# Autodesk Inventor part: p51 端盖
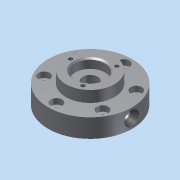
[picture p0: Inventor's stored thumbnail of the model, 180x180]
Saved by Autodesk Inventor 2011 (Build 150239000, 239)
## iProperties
Created: 2014-01
Part Number: p51 端盖
Document SubType Name: Modeling
Designer: Administrator
Density: 1 g/cm^3
Author: Administrator
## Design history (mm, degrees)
sketch "草图1"
  geometry: C1 r 45 at (0, 0); 1 further point
  constraints: 1 centre point, 1 coincident
  dimensions: "d0" = 90 diameter of C1
extrude "拉伸1" new body sketch "草图1" distance "d1" = 20; taper "d2" = 0 deg
sketch "草图2"
  geometry: C1 r 45 at (0, 0) reference; C2 r 26 at (0, 0)
  constraints: 1 centre point, 1 coincident
  dimensions: "d3" = 52 diameter of C2
extrude "拉伸2" join sketch "草图2" distance "d4" = 12; taper "d5" = 0 deg
sketch "草图3"
  geometry: C1 r 45 at (0, 0) reference; C2 r 27.5 at (0, 0)
  constraints: 1 centre point, 1 coincident
  dimensions: "d6" = 55 diameter of C2
extrude "拉伸3" join sketch "草图3" distance "d7" = 5; taper "d8" = 0 deg
hole "Hole1" diameter "d11" = 16; stored, may be unused: countersink angle "d15" = 90 deg, drill point angle "d17" = 0 deg; dims "d9" = 10, "d10" = 10, "d12" = 6, "d13" = 32, "d14" = 10, "d16" = 32
sketch "草图4" dims "d18" = 42
  geometry: C1 r 26 at (0, 0) reference; C2 r 3 at (-21, 0); 1 further point
  constraints: 1 centre point, 1 coincident, 1 horizontal alignment, 2 other
  dimensions: "d19" = 6 diameter of C2
hole "Hole2" sketch "草图4" at (-21, 0) diameter "d20" = 4.134; stored, may be unused: countersink angle "d24" = 90 deg, drill point angle "d26" = 118 deg; dims "d21" = 13, "d22" = 32, "d23" = 10, "d25" = 15
pattern_circular "环形阵列1" dims angle "d28" = 360 deg
sketch "草图5" dims "d30" = 72.5
  geometry: C1 r 45 at (0, 0) reference; C2 r 4.362 at (0, 36.25); 1 further point
  constraints: 1 centre point, 1 coincident, 1 vertical alignment, 2 other
hole "Hole3" sketch "草图5" at (0, 36.25) diameter "d31" = 6; stored, may be unused: countersink angle "d35" = 90 deg, drill point angle "d37" = 118 deg; dims "d32" = 13, "d33" = 12, "d34" = 6, "d36" = 15
pattern_circular "环形阵列2" dims angle "d39" = 360 deg
chamfer "倒角1" distance "d41" = 1.5; stored, may be unused: second distance "d42" = 2, angle "d43" = 45 deg
hole "Hole4" diameter "d46" = 35; stored, may be unused: countersink angle "d50" = 90 deg, drill point angle "d52" = 0 deg; dims "d44" = 10, "d45" = 10, "d47" = 13, "d48" = 12, "d49" = 6, "d51" = 5
fillet "圆角1" dims "d53" = 2
sketch "草图6"
  geometry: L1 (45, 0)-(45, 20) reference; L2 (-45, 20)-(45, 20) reference; L3 (-45, 0)-(45, 0) reference; L4 (-45, 0)-(-45, 20) reference; L5 (-45, 10)-(-45, 1.996); L6 (-45, 10)-(-37.745, 10); L7 (-37.745, 10)-(-37.745, 5); L8 (-37.745, 5)-(-45, 1.996); L9 (-37.745, 10)-(-16.745, 10); L10 (-16.745, 10)-(-16.745, 5); L11 (-16.745, 5)-(-37.745, 5); L12 (-16.745, 5)-(-12.099, 10); L13 (-12.099, 10)-(-16.745, 10); 1 further point
  constraints: 18 end point, 4 perpendicular, 1 midpoint, 1 parallel, 1 point on line
  dimensions: "d54" = 5 distance of L6.end L7.end; "d55" = 21 distance of L6.end L9.end; "d56" = 5 distance of L9.end L10.end
revolve "旋转1" sketch "草图6" stored, may be unused: angle "d57" = 90 deg
node "工作平面1"
sketch "草图7" dims "d59" = 35
  geometry: L1 (16.745, 5)-(37.745, 5) reference; L2 (37.745, 5)-(44.332, 7.727) reference; L3 (37.745, -5)-(37.745, 5) reference; L4 (16.745, -5)-(16.745, 5) reference; C1 r 27.5 at (0, 0) reference; C2 r 15.5 at (0, 0) reference; C3 r 26 at (0, 0) reference; C4 r 5 at (17.5, 0); 3 further points
  constraints: 1 centre point, 1 coincident, 1 horizontal alignment, 3 other
  dimensions: "d60" = 10 diameter of C4
hole "Hole5" sketch "草图7" at (17.5, 0) diameter "d61" = 10; stored, may be unused: countersink angle "d65" = 90 deg, drill point angle "d67" = 118 deg; dims "d62" = 13, "d63" = 12, "d64" = 6, "d66" = 10
feature "螺纹1" dims "d68" = 10, "d69" = 0
node "实体1"
other parameters: "d58" = -5
